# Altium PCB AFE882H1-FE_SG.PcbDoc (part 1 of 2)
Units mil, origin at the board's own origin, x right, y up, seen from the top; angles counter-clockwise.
Board outline 2755.91 x 1181.1 mil, 4 copper layers (Top Layer, Int1 (GND), Int2 (PWR), Bottom Layer), stack 53.912 mil thick; 101 components, 57 nets, 291 pads, 95 vias.
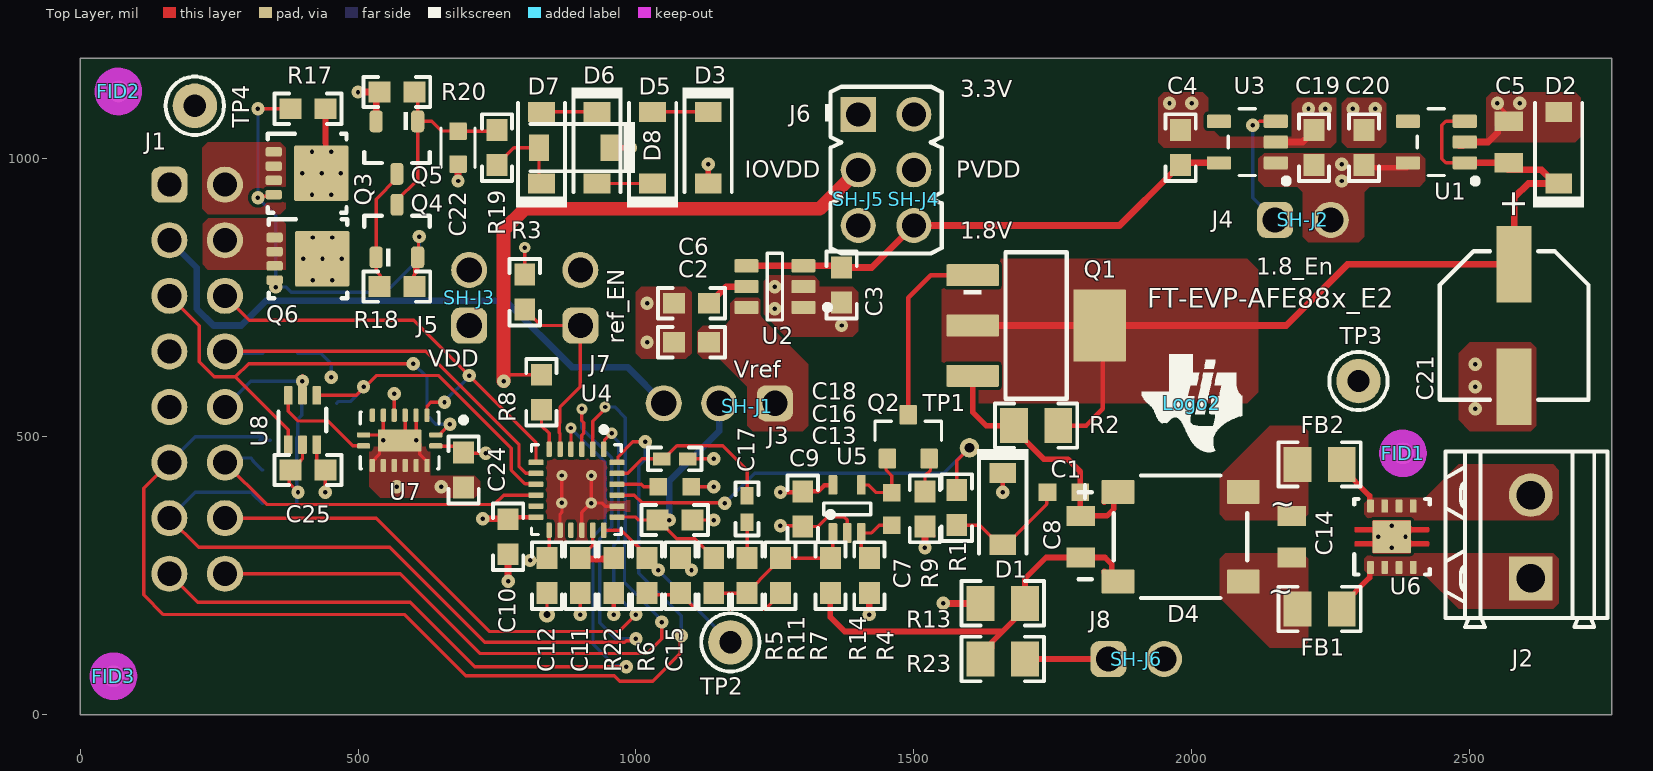
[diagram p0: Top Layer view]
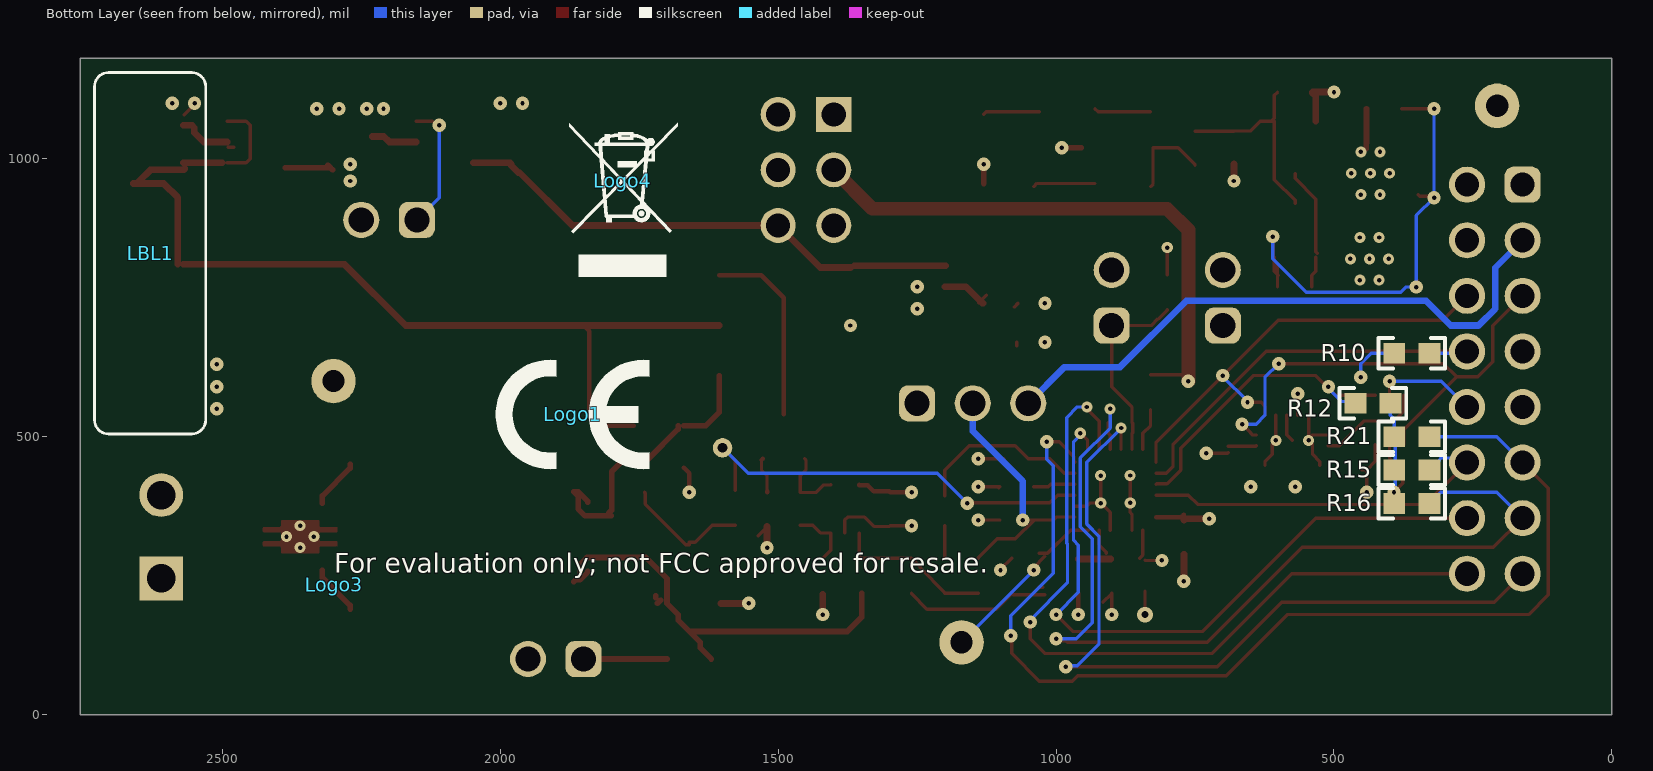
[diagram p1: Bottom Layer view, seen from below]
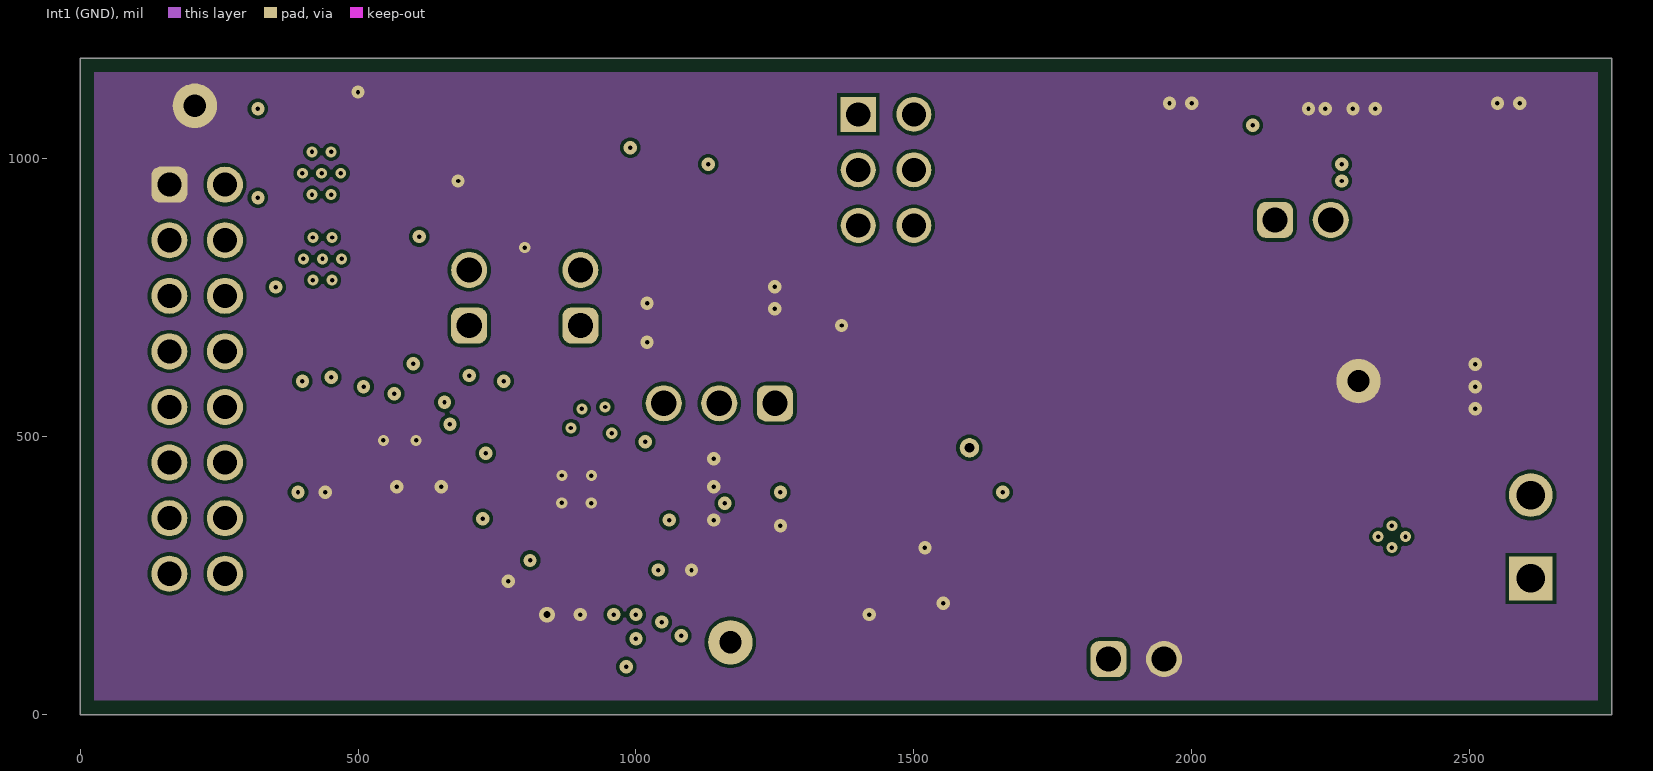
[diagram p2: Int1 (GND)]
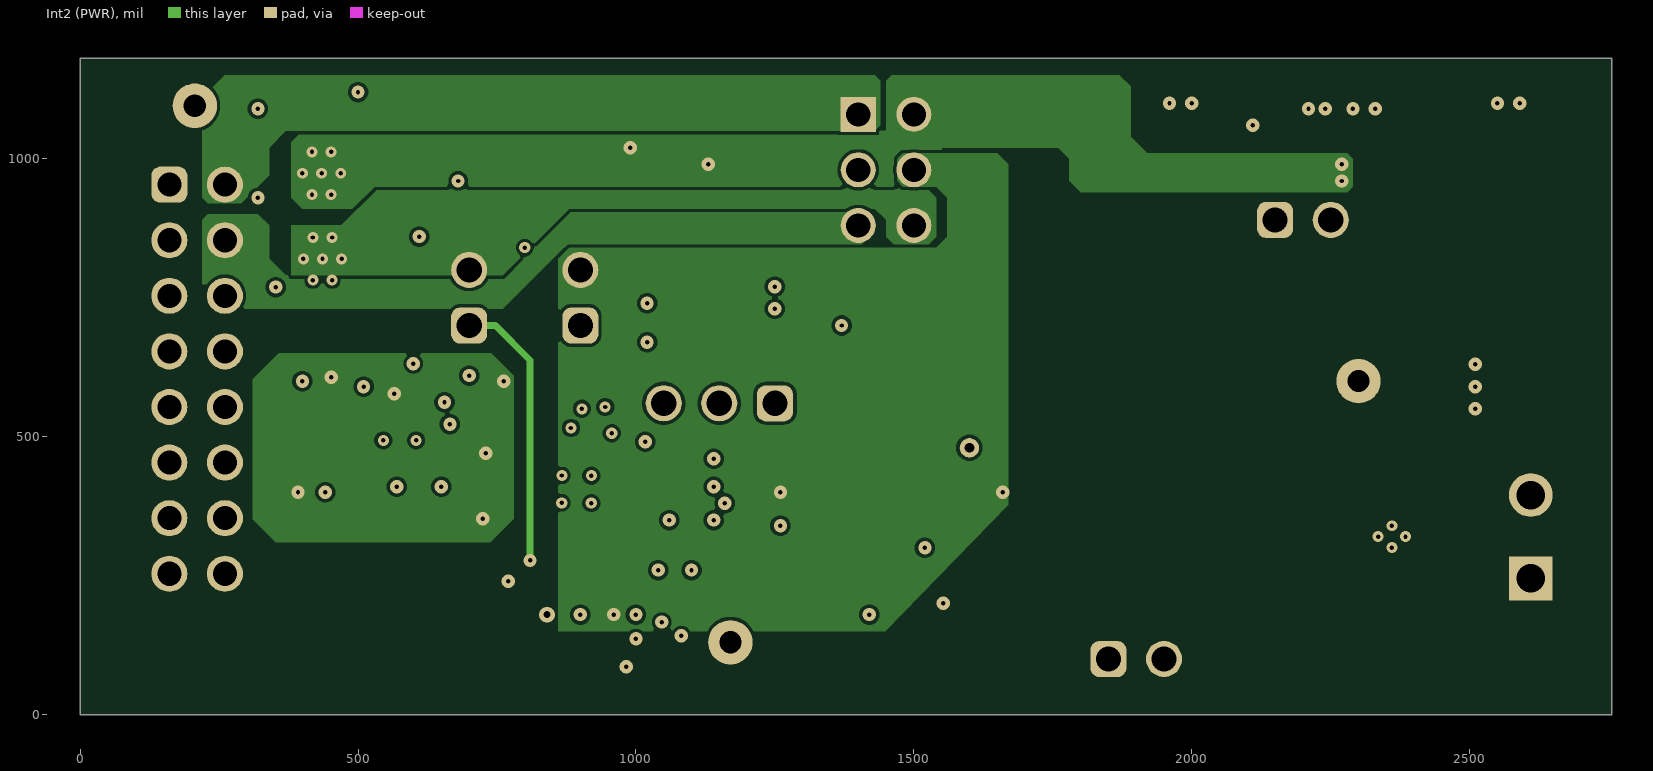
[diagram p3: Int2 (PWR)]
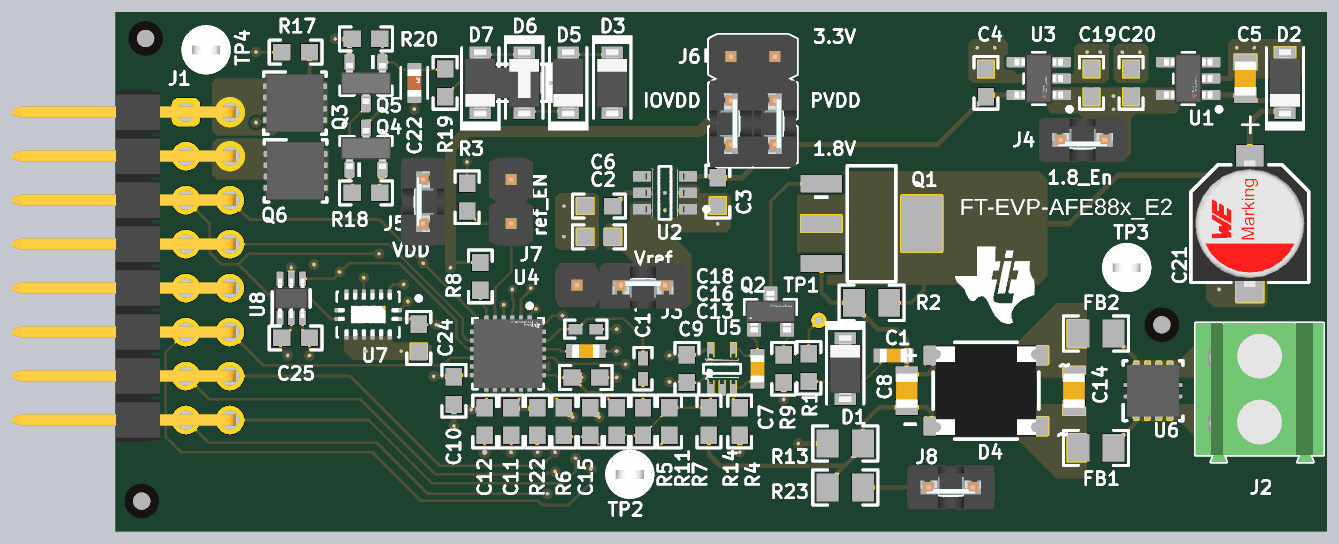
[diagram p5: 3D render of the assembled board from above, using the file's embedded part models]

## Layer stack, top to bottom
Top Solder: solder mask 1, SM-001, Dk 4
Top Layer: signal copper 1.378
Dielectric 1: prepreg 5.1, PP-017, Dk 4.3
Dielectric 2: prepreg 5.1, PP-017, Dk 4.3
Int1 (GND): signal copper 1.378
Dielectric 3: core 28, Core-039, Dk 4.8
Int2 (PWR): signal copper 1.378
Dielectric 4: prepreg 5.1, PP-017, Dk 4.3
Dielectric 5: prepreg 5.1, PP-017, Dk 4.3
Bottom Layer: signal copper 1.378
Bottom Solder: solder mask 1, SM-001, Dk 4

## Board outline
0,0 2755.91,0 2755.91,1181.1 0,1181.1

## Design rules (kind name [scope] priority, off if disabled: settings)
AcuteAngle [All] p1 off: minimum=4.50000000000000E+0001 checktracksonly=FALSE
AssemblyTestPointUsage [All] p1: valid=2
BoardOutlineClearance BoardOutlineClearance_MountingHoles [OnCopper and InComponentClass('Mounting Holes')] p1: gap=39.37 ignorepadtopadclearanceinfootprint=FALSE
BoardOutlineClearance BoardOutlineClearance_Poly [OnCopper and IsPoly] p2: gap=25 ignorepadtopadclearanceinfootprint=FALSE
BoardOutlineClearance [OnCopper and Not InComponentClass('Logo') and not InComponentClass('FiducialMark') and not InRegion(1000,500,4000,800) and not InPoly] p3: gap=40 ignorepadtopadclearanceinfootprint=FALSE
Clearance Clearance_Keepouts [((IsTrack Or IsArc) And Not InPoly) And IsFree and IsKeepOut vs ((IsTrack Or IsArc) And Not InPoly) And IsFree and IsKeepOut] p1: gap=0 ignorepadtopadclearanceinfootprint=FALSE
Clearance Clearance_Poly [InPolygon] p2: gap=6 ignorepadtopadclearanceinfootprint=TRUE
Clearance Clearance_FiducialMark [IsKeepOut and InComponentClass('FiducialMark') vs IsPad and InComponentClass('FiducialMark')] p3: gap=0 ignorepadtopadclearanceinfootprint=FALSE
Clearance [All] p4: gap=6 ignorepadtopadclearanceinfootprint=TRUE
ComponentClearance ComponentClearance_D8_D7_d6 [InComponent('D8') or InComponent('D7') or InComponent('D6')] p1: gap=0 collisioncheckmode=3 verticalgap=0 showdistances=FALSE
ComponentClearance ComponentClearance_J6 [InComponent('J6') or InComponent('SH-J4') or InComponent('SH-J5')] p2: gap=0 collisioncheckmode=3 verticalgap=0 showdistances=FALSE
ComponentClearance ComponentClearance_J5 [InComponent('J5') or InComponent('SH-J3')] p3: gap=0 collisioncheckmode=3 verticalgap=0 showdistances=FALSE
ComponentClearance ComponentClearance_MountingHoles_FiducialMarks [InComponentClass('Mounting Holes') vs InComponentClass('FiducialMark')] p4: gap=50 collisioncheckmode=3 verticalgap=10 showdistances=FALSE
ComponentClearance ComponentClearance_Shunt [InComponentClass('Header') vs InComponentClass('Shunt')] p5: gap=0 collisioncheckmode=3 verticalgap=0 showdistances=FALSE
ComponentClearance ComponentClearance_Logo [InComponentClass('Logo')] p6: gap=30 collisioncheckmode=3 verticalgap=10 showdistances=FALSE
ComponentClearance ComponentClearance_ScrewToNut [(HasFootprint('NY PMS 440 0025 PH')) vs (HasFootprint('Keystone_1902C'))] p7: gap=5 collisioncheckmode=3 verticalgap=10 showdistances=FALSE
ComponentClearance ComponentClearance_MountingHoles [InComponentClass('Mounting Holes')] p8: gap=100 collisioncheckmode=3 verticalgap=100000 showdistances=FALSE
ComponentClearance ComponentClearance_SmallPassives [HasFootprint('0201*') or HasFootprint('0402*') or HasFootprint('0508') or HasFootprint('0603*') or HasFootprint('0612') or HasFootprint('0805*') or HasFootprint('0815*') or HasFootprint('0830*') or HasFootprint('1206*') or HasFootprint('1210*') or HasFootprint('1808*') or HasFootprint('1812*') or HasFootprint('1825*') or HasFootprint('2010*') or HasFootprint('2220*') or HasFootprint('2225*') or HasFootprint('2512*') or HasFootprint('2728*') or HasFootprint('3518*') vs HasFootprint('0201*') or HasFootprint('0402*') or HasFootprint('0508') or HasFootprint('0603*') or HasFootprint('0612') or HasFootprint('0805*') or HasFootprint('0815*') or HasFootprint('0830*') or HasFootprint('1206*') or HasFootprint('1210*') or HasFootprint('1808*') or HasFootprint('1812*') or HasFootprint('1825*') or HasFootprint('2010*') or HasFootprint('2220*') or HasFootprint('2225*') or HasFootprint('2512*') or HasFootprint('2728*') or HasFootprint('3518*')] p9: gap=14.96 collisioncheckmode=3 verticalgap=10 showdistances=FALSE
ComponentClearance ComponentClearance_THtoSMT [IsThruComponent vs IsSMTComponent] p10: gap=20 collisioncheckmode=3 verticalgap=20 showdistances=FALSE
ComponentClearance ComponentClearance_THtoTH [IsThruComponent vs IsThruComponent] p11: gap=20 collisioncheckmode=3 verticalgap=30 showdistances=FALSE
ComponentClearance [All] p12: gap=20 collisioncheckmode=3 verticalgap=10 showdistances=FALSE
DiffPairsRouting [All] p1: maxlimit=100 minlimit=10 mostfreqgap=10 toplayer_minwidth=15 toplayer_maxwidth=15 toplayer_prefwidth=15 midlayer1_minwidth=15 midlayer1_maxwidth=15 midlayer1_prefwidth=15 midlayer2_minwidth=15 midlayer2_maxwidth=15 midlayer2_prefwidth=15 bottomlayer_minwidth=15 bottomlayer_maxwidth=15 bottomlayer_prefwidth=15 maxuncoupledlength=1000
FabricationTestPointUsage TestPointUsage [All] p1: valid=2 allowmultiple=FALSE
FabricationTestpoint Testpoint [All] p1: side=3 testpointundercomponent=TRUE minsize=40 maxsize=100 preferedsize=60 minholesize=0 maxholesize=40 preferedholesize=32 testpointgrid=1 allowsidetop=TRUE allowsidebottom=TRUE usegrid=TRUE gridtolerance=0.01
FanoutControl Fanout_LCC [IsLCC] p1: bgadir=Out bgaviamode=Centered fanoutstyle=Auto fanoutdirection=Alternating viagrid=1 // Fanout_LCC (Default Rule)
FanoutControl Fanout_BGA [IsBGA] p2: bgadir=Out bgaviamode=Centered fanoutstyle=Auto fanoutdirection=Alternating viagrid=1 // Fanout_BGA (Default Rule)
FanoutControl Fanout_Default [All] p4: bgadir=Out bgaviamode=Centered fanoutstyle=Auto fanoutdirection=Alternating viagrid=1 // Fanout_Default (Default Rule)
FanoutControl Fanout_Small [(CompPinCount < 5)] p5: bgadir=Out bgaviamode=Centered fanoutstyle=Auto fanoutdirection=OutThenIn viagrid=1 // Fanout_Small (Default Rule)
HoleSize [All] p1: absolutevalues=TRUE maxlimit=251 minlimit=7.87 maxpercent=80.000 minpercent=20.000
MinimumAnnularRing MinimumAnnularRing_ThermalPadVias [IsVia and InAnyComponent] p1: minimumring=5.91
MinimumAnnularRing [All] p2: minimumring=6
MinimumSolderMaskSliver MinimumSolderMaskSliver_Logo [InComponentClass('Logo') vs InComponentClass('Logo')] p1: minsoldermaskwidth=0.7
MinimumSolderMaskSliver [All] p2: minsoldermaskwidth=3.94
PlaneConnect [All] p1: planeconnectstyle=Relief reliefexpansion=10 reliefentries=4 reliefconductorwidth=10 reliefairgap=10
PolygonConnect PolygonConnect_6 [All vs IsNamedPolygon('TOP_LAYER_GND_P000')] p1: connectstyle=Direct reliefconductorwidth=10 reliefentries=4 polygonreliefangle="90 Angle" airgapwidth=10
PolygonConnect PolygonConnect_5 [All vs IsNamedPolygon('TOP_LAYER_GND_P000')] p2: connectstyle=Direct reliefconductorwidth=10 reliefentries=4 polygonreliefangle="90 Angle" airgapwidth=10
PolygonConnect PolygonConnect_4 [All vs IsNamedPolygon('TOP_LAYER_GND_P001')] p3: connectstyle=Direct reliefconductorwidth=10 reliefentries=4 polygonreliefangle="90 Angle" airgapwidth=10
PolygonConnect PolygonConnect_3 [All vs IsNamedPolygon('TOP_LAYER_GND_P001')] p4: thpad.connectstyle=Direct thpad.reliefconductorwidth=10 thpad.reliefentries=4 thpad.polygonreliefangle="90 Angle" thpad.airgapwidth=10 smdpad.connectstyle=Direct smdpad.reliefconductorwidth=10 smdpad.reliefentries=4 smdpad.polygonreliefangle="90 Angle" smdpad.airgapwidth=10 via.connectstyle=Relief via.reliefconductorwidth=10 via.reliefentries=4 via.polygonreliefangle="90 Angle" via.airgapwidth=10
PolygonConnect PolygonConnect_2 [All vs IsNamedPolygon('TOP_LAYER_NONET_P000')] p5: thpad.connectstyle=Direct thpad.reliefconductorwidth=10 thpad.reliefentries=4 thpad.polygonreliefangle="90 Angle" thpad.airgapwidth=10 smdpad.connectstyle=Direct smdpad.reliefconductorwidth=10 smdpad.reliefentries=4 smdpad.polygonreliefangle="90 Angle" smdpad.airgapwidth=10 via.connectstyle=Relief via.reliefconductorwidth=10 via.reliefentries=4 via.polygonreliefangle="90 Angle" via.airgapwidth=10
PolygonConnect PolygonConnect_1 [All vs IsNamedPolygon('TOP_LAYER_NONET_P000')] p6: thpad.connectstyle=Direct thpad.reliefconductorwidth=10 thpad.reliefentries=4 thpad.polygonreliefangle="90 Angle" thpad.airgapwidth=10 smdpad.connectstyle=Direct smdpad.reliefconductorwidth=10 smdpad.reliefentries=4 smdpad.polygonreliefangle="90 Angle" smdpad.airgapwidth=10 via.connectstyle=Relief via.reliefconductorwidth=10 via.reliefentries=4 via.polygonreliefangle="90 Angle" via.airgapwidth=10
PolygonConnect [All] p7: connectstyle=Direct reliefconductorwidth=10 reliefentries=4 polygonreliefangle="90 Angle" airgapwidth=10
RoutingVias ThermalPadVias [IsVia and InAnyComponent] p1: holewidth=7.87 width=19.68 viastyle="Through Hole" minholewidth=7.87 minwidth=19.68 maxholewidth=12.99 maxwidth=23.62
RoutingVias [All] p2: holewidth=8 width=24 viastyle="Through Hole" minholewidth=8 minwidth=20 maxholewidth=40 maxwidth=65
SilkToBoardRegionClearance [Not ((IsComment or IsDesignator) And (Hide <> 'False')) and not InRegion(1000,500,4000,800)] p1:
SilkToSilkClearance SilkToSilkClearance_Pb-FreeLogo [(HasFootprint('Pb-Free_Overlay_Medium') OR HasFootprint('Pb-Free_Overlay_Small')) vs (HasFootprint('Pb-Free_Overlay_Medium') OR HasFootprint('Pb-Free_Overlay_Small'))] p1 off: silktosilkclearance=0
SilkToSilkClearance [All] p2: silktosilkclearance=3.94
SilkToSolderMaskClearance SilkToComponentPadClearance [(IsPad or IsFill or IsRegion) and InAnycomponent] p1 off: minsilkscreentomaskgap=5 clearancetoexposedcopper=TRUE
SilkToSolderMaskClearance "Silk to Solder Mask Opening" [All] p2 off: minsilkscreentomaskgap=3.94 clearancetoexposedcopper=FALSE
SolderMaskExpansion [All] p1: expansion=1.97 istentingtop=FALSE
SupplyNets "Schematic Supply Nets_8" [InNet('VREF_AFE')] p1: voltage=0.000
SupplyNets "Schematic Supply Nets_7" [InNet('VREF_EXT')] p2: voltage=0.000
SupplyNets "Schematic Supply Nets_5" [InNet('VDD-1V8')] p3: voltage=0.000
SupplyNets "Schematic Supply Nets_4" [InNet('PVDD')] p4: voltage=0.000
SupplyNets "Schematic Supply Nets_3" [InNet('IOVDD')] p5: voltage=0.000
SupplyNets "Schematic Supply Nets_2" [InNet('GND')] p6: voltage=0.000
SupplyNets "Schematic Supply Nets_1" [InNet('VDD_int')] p7: voltage=0.000
SupplyNets "Schematic Supply Nets" [InNet('VDD-3V3')] p8: voltage=0.000
UnRoutedNet [All] p1: checkbadconnections=TRUE
Width [All] p1: maxlimit=100 minlimit=6 preferedwidth=6 minimp=50.000000 maximp=50.000000 favimp=50.000000 checkconnectedcopper=TRUE
14 further rules are at their usual default settings.

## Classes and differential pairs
component class Shunt: SH-J1 SH-J2 SH-J3 SH-J4 SH-J5 SH-J6
component class Logo: Logo2
component class Header: J1 J3 J4 J5 J6 J7 J8
component class AFE882H1-FE_BlankSheet: C1 C2 C3 C4 C5 C6 C7 C8 C9 C10 C11 C12 C13 C14 C15 C16 C17 C18 C19 C20 C21 C22 C24 C25 D1 D2 D3 D4 D5 D6 D7 D8 FB1 FB2 J1 J2 J3 J4 J5 J6 J7 J8 Q1 Q2 Q3 Q4 Q5 Q6 R1 R2 R3 R4 R5 R6 R7 R8 R9 R10 R11 R12 R13 R14 R15 R16 R17 R18 R19 R20 R21 R22 R23 SH-J1 SH-J2 SH-J3 SH-J4 SH-J5 SH-J6 TP1 TP2 TP3 TP4 U1 U2 U3 U4 U5 U6 U7 U8
component class AFE882H1-FE_Hardware: FID1 FID2 FID3 H9 LBL1 Logo1 Logo2 Logo3 Logo4 ZZ1 ZZ2 ZZ3 ZZ4
component class FiducialMark: FID1 FID2 FID3
component class AssemblyNote: ZZ1 ZZ2 ZZ3 ZZ4
component class Label: LBL1

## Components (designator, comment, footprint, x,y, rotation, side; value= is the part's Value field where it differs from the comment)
C1 "885012006015" WCAP-CSGP_0603_L1.6W0.8H0.8_Reflow 1770,400 r0 top value=2.2nF
C2 "885012206052" 0603 1100,670 r180 top value=1uF
C3 "885012206020" 0603 1370,772.83 r270 top value=0.1uF
C4 "885012206052" 0603 1980,1020 r90 top value=1uF
C5 "885012207052" WCAP-CSGP_0805_L2W1.25H1.25 2570,1030 r270 top value=2.2µF
C6 "885012206020" 0603 1100,740 r180 top value=0.1uF
C7 "885012006010" WCAP-CSGP_0603_L1.6W0.8H0.8_Reflow 1460,370 r90 top value=220pF
C8 "885012207086" WCAP-CSGP_0805_L2W1.25H0.8_Reflow 1800,320 r90 top value=1nF
C9 "885012206020" 0603 1300,370 r270 top value=0.1uF
C10 "885012206020" 0603 770,320 r270 top value=0.1uF
C11 "885012206020" 0603 900,250 r270 top value=0.1uF
C12 "885012206052" 0603 840,250 r270 top value=1uF
C13 "885012206020" 0603 1070,350 r0 top value=0.1uF
C14 "885012207086" WCAP-CSGP_0805_L2W1.25H0.8_Reflow 2180,320 r270 top value=1nF
C15 "885012206091" 0603 1080,250 r90 top value=0.022uF
C16 "885012006013" WCAP-CSGP_0603_L1.6W0.8H0.8_Reflow 1070,410 r0 top value=680pF
C17 "885012205061" 0402 1200,370 r90 top value=1000pF
C18 "885012205061" 0402 1070,460 r180 top value=1000pF
C19 "885012206052" 0603 2220,1020 r90 top value=1uF
C20 "885012206052" 0603 2310,1020 r90 top value=1uF
C21 "865230143004" WCAP-AS5H_D6.3H5.5 2580,700 r90 top value=100µF
C22 "885012106005" FP-885012106005_0603-MFG 680,1020 r90 top value=4.7µF
C24 "885012206020" 0603 690,440 r270 top value=0.1uF
C25 "885012206020" 0603 410,440 r0 top value=0.1uF
D1 "1N4148W-TP" SOD-123 1660,370 r270 top value=100V
D2 "MMSZ4688-HE3-08" SOD-123 2660,1020 r90 top value=4.7V
D3 "1N4148W-TP" SOD-123 1130,1020 r270 top value=100V
D4 "CD-MBL206SL" CD-MBL2xxS 1980,320 r0 top value=600V
D5 "1N4148W-TP" SOD-123 1030,1020 r90 top value=100V
D6 "1N4148W-TP" SOD-123 930,1020 r270 top value=100V
D7 "1N4148W-TP" SOD-123 830,1020 r90 top value=100V
D8 "CMHZ4681" SOD-123 890,1020 r180 top value=2.4V
FB1 "742792041" 0805_HV 2230,190 r0 top value="600 ohm"
FB2 "742792041" 0805_HV 2230,450 r0 top value="600 ohm"
FID1 "Fiducial" Fiducial10-20 2380,470 r0 top
FID2 "Fiducial" Fiducial10-20 68.9,1121.1 r0 top
FID3 "Fiducial" Fiducial10-20 60,68.9 r0 top
J1 "61301621021" Wurth_61301621021 210.52,603.39 r0 top
J2 "691214310002" Wurth_691214310002 2610,320 r90 top
J3 "61300311121" WURTH_61300311121 1150,560 r180 top
J4 "61300211121" WURTH_61300211121 2200,890 r0 top
J5 "61300211121" WURTH_61300211121 700,750 r90 top
J6 "61300621121" Wurth_61300621121 1450,980 r0 top
J7 "61300211121" WURTH_61300211121 900,750 r90 top
J8 "61300211121" WURTH_61300211121 1900,100 r0 top
LBL1 "THT-14-423-10" Label_650x200 2630,830 r90 bottom
Logo1 "CE Mark" CE_Mark_5mm 1870,540 r180 bottom
Logo2 "Texas Instruments" TI_Symbol_Overlay_Small 2000,560 r0 top
Logo3 "FCC disclaimer" FCC_disclaimer 2298.43,233.22 r180 bottom
Logo4 "WEEE logo" WEEE_Minimum 1780,960 r180 bottom
Q1 "PZT2907A" SOT-223 1720,700 r0 top value="60 V"
Q2 "SMMBT3904LT3G" FP-SMMBT3904LT3G_SOT23-MFG 1490,500 r90 top value=40V
Q3 "CSD25404Q3" DQG0008A 408.35,973.92 r0 top value=-20V
Q4 "BC858CLT1G" SOT-23 570,870 r90 top value="30 V"
Q5 "BC847CLT1G" SOT-23 570,1020 r270 top value="45 V"
Q6 "CSD25404Q3" DQG0008A 410,820 r0 top value=-20V
R1 "RC0603JR-071KL" 0603 1577.06,372.39 r270 top value=1.0k
R2 "RG2012P-123-B-T5" 0805_HV 1720,520 r180 top value=12.0k
R3 "RC0603FR-072M21L" 0603 800,760 r90 top value=2.21Meg
R4 "RG1608P-203-B-T5" 0603 1420,250 r90 top value=20.0k
R5 "RT0603BRD07412KL" 0603 1140,250 r270 top value=412k
R6 "RG1608P-203-B-T5" 0603 1020,250 r90 top value=20.0k
R7 "RG1608P-104-B-T5" 0603 1260,250 r90 top value=100k
R8 "CRCW06031M00JNEA" 0603 830,580 r90 top value=1.0Meg
R9 "RT0603BRD074K99L" 0603 1520,370 r90 top value=4.99k
R10 "CRCW06031M00JNEA" 0603 360,650 r0 bottom value=1.0Meg
R11 "RT0603DRE07499KL" 0603 1200,250 r270 top value=499k
R12 "CRCW06031M00JNEA" 0603 430,560 r180 bottom value=1.0Meg
R13 "RT0805BRD0720RL" 0805_HV 1660,200 r180 top value=20.0
R14 "RG1608P-203-B-T5" 0603 1350,250 r90 top value=20.0k
R15 "CRCW06031M00JNEA" 0603 360,440 r0 bottom value=1.0Meg
R16 "CRCW06031M00JNEA" 0603 360,380 r0 bottom value=1.0Meg
R17 "CRCW06031M00JNEA" 0603 410,1090 r0 top value=1.0Meg
R18 "M55342K12B10E0T" 0603 570,770 r0 top value=10.0k
R19 "M55342K12B10E0T" 0603 750,1020 r270 top value=10.0k
R20 "M55342K12B10E0T" 0603 570,1120 r0 top value=10.0k
R21 "M55342K12B10E0T" 0603 360,500 r0 bottom value=10.0k
R22 "RCS06030000Z0EA" 0603 960,250 r90 top value=0
R23 "RT0805BRD0720RL" 0805_HV 1660,100 r0 top value=20.0
SH-J1 "60900213421" Wurth_60900213421 1200,555 r0 top
SH-J2 "60900213421" Wurth_60900213421 2200,890 r180 top
SH-J3 "60900213421" Wurth_60900213421 700,750 r90 top
SH-J4 "60900213421" Wurth_60900213421 1500,927.48 r270 top
SH-J5 "60900213421" Wurth_60900213421 1400,927.48 r270 top
SH-J6 "60900213421" Wurth_60900213421 1900,100 r180 top
TP1 "TP_H0.45P0.75" TP_H045P075 1600,480 r0 top
TP2 "VOUT" Keystone5002 1170,130 r90 top
TP3 "GND" Keystone5002 2300,600 r90 top
TP4 "GND" Keystone5002 206.4,1095.28 r90 top
U1 "TPS7A0333DBVR" DBV0005A-MFG 2440,1030 r180 top
U2 "REF35125QDBVR" DBV0006A-MFG 1250,770 r180 top
U3 "TPS7A0318DBVR" DBV0005A-MFG 2100,1030 r180 top
U4 "AFE882H1RRUT" RRU0024A-MFG 892.98,404.55 r270 top
U5 "OPA391DCKT" DCK0005A-MFG 1380,370 r90 top
U6 "TVS3301DRBR" DRB0008A 2360,320 r90 top
U7 "SN74LV8T165BQBR" BQB0016A-MFG 575,493.29 r270 top
U8 "TMUX1219DCKR" DCK0006A_N 400,530 r90 top
ZZ1 "This Assembly Note is for PCB labels only" AssemblyNoteLabel 185,3938 r0 top
ZZ2 "These assemblies are ESD sensitive, ESD precautions shall be observed." AssemblyNote 185,3829.11 r0 top
ZZ3 "These assemblies must be clean and free from flux and all contaminants. Use of no clean flux is not acceptable." AssemblyNote 185,3740.56 r0 top
ZZ4 "These assemblies must comply with workmanship standards IPC-A-610 Class 2, unless otherwise specified." AssemblyNote 185,3652 r0 top

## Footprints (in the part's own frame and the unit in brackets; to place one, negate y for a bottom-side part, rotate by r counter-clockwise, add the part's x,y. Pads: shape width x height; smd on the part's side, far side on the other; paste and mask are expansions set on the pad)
0402 [mm] "0402 from SM-752 data"
  rect 0.8x0.6 smd: 1(-0.6,0) 2(0.6,0)
  silkscreen extent -1.22,-0.52 1.22,0.52, body extent -0.55,-0.3 0.55,0.3, height 0.6
0603 [mm] "0603 from SM-752 data"
  rect 1x0.95 smd: 1(-0.8,0) 2(0.8,0)
  silkscreen extent -1.52,-0.69 1.52,0.69, body extent -0.87,-0.47 0.87,0.47, height 1
0805_HV [mil] "0805 with 30mil clearance between pads"
  rect 50x63 smd: 1(-40,0) 2(40,0)
  silkscreen extent -74,-40 74,40, body extent -43,-29 43,29, height 57
AssemblyNote [mil] "Assembly Note"
AssemblyNoteLabel [mil] "Assembly Note for PCB Labels"
BQB0016A-MFG [mm]
  rrect42% 0.24x0.6 smd paste+0 mask+0: 1(-0.25,1.65) 8(-0.25,-1.65) 9(0.25,-1.65) 16(0.25,1.65)
  rrect42% 0.6x0.24 smd paste+0 mask+0: 2(-1.15,1.25) 3(-1.15,0.75) 4(-1.15,0.25) 5(-1.15,-0.25) 6(-1.15,-0.75) 7(-1.15,-1.25) 10(1.15,-1.25) 11(1.15,-0.75) 12(1.15,-0.25) 13(1.15,0.25) 14(1.15,0.75) 15(1.15,1.25)
  rrect10% 1x2 smd paste-1000 mask+0: 17(0,0)
  silkscreen extent -1.3,-1.8 1.3,3.05, body extent -1.55,-2.05 1.55,2.05, height 0.25
CD-MBL2xxS [mm] "SMD, 4-Leads, Body 5.72x4.1mm"
  rrect9% 1.5x1.1 smd: 1(-2.86,2.05) 2(2.86,2.05) 3(2.86,-2.05) 4(-2.86,-2.05)
  silkscreen extent -4.67,-2.8 3.05,2.8, body extent -2.9,-2.65 2.9,2.65, height 1.02
CE_Mark_5mm [mil] "Minimum text height for CE Mark"
  silkscreen extent -138,-98 138,98
DBV0005A-MFG [mm]
  rrect17% 1.1x0.6 smd paste+0 mask+0: 1(-1.3,0.95) 2(-1.3,0) 3(-1.3,-0.95) 4(1.3,-0.95) 5(1.3,0.95)
  silkscreen extent -1.9,-1.52 0.87,1.9, body extent -1.95,-1.78 1.95,1.78, height 0.25
DBV0006A-MFG [mm]
  rrect17% 1.1x0.6 smd paste+0 mask+0: 1(-1.3,0.95) 2(-1.3,0) 3(-1.3,-0.95) 4(1.3,-0.95) 5(1.3,0) 6(1.3,0.95)
  silkscreen extent -2.53,-1.53 0.35,1.52, body extent -1.95,-1.78 1.95,1.78, height 0.25
DCK0005A-MFG [mm]
  rrect25% 0.9x0.4 smd paste-1000 mask+0: 1(-1.1,0.65) 2(-1.1,0) 3(-1.1,-0.65) 4(1.1,-0.65) 5(1.1,0.65)
  silkscreen extent -0.38,-1.07 0.27,1.08, body extent -1.65,-1.33 1.65,1.33, height 0.25
DCK0006A_N [mm] "SOT23, 6-Leads, Body 2x1.3mm, Pitch 0.65mm, Lead Span 2.1mm, IPC Medium Density"
  rrect25% 0.85x0.4 smd: 1(-1.125,0.65) 2(-1.125,0) 3(-1.125,-0.65) 4(1.125,-0.65) 5(1.125,0) 6(1.125,0.65)
  silkscreen extent -1.5,-1.09 0.51,1.09, body extent -1.14,-1 1.14,1, height 0.95
DQG0008A [mm] "SMD, 8-Leads, Body 3.3x3.3mm, Pitch 0.65mm"
  rrect45% 0.75x0.44 smd paste-0.05 mask-0.05: 1(-1.525,0.975) 2(-1.525,0.325) 3(-1.525,-0.325) 4(-1.525,-0.975) 5(1.525,-0.975) 6(1.525,-0.325) 7(1.525,0.325) 8(1.525,0.975)
  rrect15% 0.676x1.125 on Top Paste: 9(-0.212,-0.663) 9(-0.212,0.662) 9(0.664,-0.663) 9(0.664,0.662)
  rrect6% 1.775x2.45 on Top Solder: 9(0.327,0)
  rrect8% 2.5x2.55 smd paste-1.5 mask-1.5: 9(0.65,0)
  rrect29% 0.5x0.34 on Top Solder: 9(1.175,-0.975) 9(1.175,-0.325) 9(1.175,0.325) 9(1.175,0.975)
  silkscreen extent -1.8,-1.8 1.8,1.8, body extent -1.65,-1.65 1.65,1.65, height 1.1
DRB0008A [mm] "VSON-8"
  rrect32% 0.6x0.31 smd: 1(-1.4,0.975) 2(-1.4,0.325) 3(-1.4,-0.325) 4(-1.4,-0.975) 5(1.4,-0.975) 6(1.4,-0.325) 7(1.4,0.325) 8(1.4,0.975)
  rrect7% 1.5x1.75 smd paste-0.75: 9(0,0)
  Top Layer region: -0.7,-0.875 -0.49,-0.875 -0.471,-0.879 -0.455,-0.89 -0.444,-0.906 -0.44,-0.925 -0.44,-0.925 -0.44,-1.65 -0.436,-1.669 -0.425,-1.685 -0.409,-1.696 -0.39,-1.7 -0.39,-1.7 -0.26,-1.7 -0.241,-1.696 -0.225,-1.685 -0.214,-1.669 -0.21,-1.65 -0.21,-1.65 -0.21,-0.925 -0.206,-0.906 -0.195,-0.89 -0.179,-0.879 -0.16,-0.875 -0.16,-0.875 0.16,-0.875 0.179,-0.879 0.195,-0.89 0.206,-0.906 0.21,-0.925 0.21,-0.925 0.21,-1.65 0.21,-1.65 0.214,-1.669 0.225,-1.685 0.241,-1.696 0.26,-1.7 0.26,-1.7 0.39,-1.7 0.409,-1.696 0.425,-1.685 0.436,-1.669 0.44,-1.65 0.44,-1.65 0.44,-0.925 0.444,-0.906 0.455,-0.89 0.471,-0.879 0.49,-0.875 0.49,-0.875 0.7,-0.875 0.719,-0.871 0.735,-0.86 0.746,-0.844 0.75,-0.825 0.75,-0.825 0.75,0.825 0.746,0.844 0.735,0.86 0.719,0.871 0.7,0.875 0.7,0.875 0.49,0.875 0.471,0.879 0.455,0.89 0.444,0.906 0.44,0.925 0.44,0.925 0.44,1.65 0.436,1.669 0.425,1.685 0.409,1.696 0.39,1.7 0.39,1.7 0.26,1.7 0.241,1.696 0.225,1.685 0.214,1.669 0.21,1.65 0.21,1.65 0.21,1.65 0.21,0.925 0.206,0.906 0.195,0.89 0.179,0.879 0.16,0.875 0.16,0.875 -0.16,0.875 -0.179,0.879 -0.195,0.89 -0.206,0.906 -0.21,0.925 -0.21,0.925 -0.21,1.65 -0.214,1.669 -0.225,1.685 -0.241,1.696 -0.26,1.7 -0.26,1.7 -0.39,1.7 -0.409,1.696 -0.425,1.685 -0.436,1.669 -0.44,1.65 -0.44,1.65 -0.44,0.925 -0.444,0.906 -0.455,0.89 -0.471,0.879 -0.49,0.875 -0.49,0.875 -0.7,0.875 -0.719,0.871 -0.735,0.86 -0.746,0.844 -0.75,0.825 -0.75,0.825 -0.75,-0.825 -0.746,-0.844 -0.735,-0.86 -0.719,-0.871 -0.7,-0.875
  silkscreen extent -1.73,-1.73 1.73,1.73, body extent -1.5,-1.5 1.5,1.5, height 0.77
FCC_disclaimer [mil]
Fiducial10-20 [mm]
  round 1 smd mask+0.5: 1(0,0)
  Top Layer keep-out circle w1.178: c0,0 r0.5
FP-885012106005_0603-MFG [mm]
  rrect13% 0.8x0.8 smd paste+0 mask+0: 1(-0.75,0) 2(0.75,0)
  silkscreen extent -0.9,-0.77 0.9,0.77, body extent -1.25,-0.6 1.25,0.6, height 0.25
FP-SMMBT3904LT3G_SOT23-MFG [mm]
  rrect13% 0.9x0.8 smd paste+0 mask+0: 1(-1,0.95) 2(-1,-0.95) 3(1,0)
  silkscreen extent -0.18,-1.52 0.7,1.52, body extent -1.55,-1.62 1.55,1.62, height 0.25
Keystone5002 [mil] "For Keystone 500x miniature loop terminals"
  round 80 hole 40: 1(0,0)
  silkscreen extent -52,-52 52,52, body extent -49,-49 49,49, height 182
Label_650x200 [mil] "Thermal Transfer Label"
  round 1 on Mech14: 0(0,0)
  silkscreen extent -325,-100 325,100, body extent -325,-100 325,100, height 1
RRU0024A-MFG [mm]
  rrect40% 0.7x0.25 smd paste+0 mask+0: 1(-1.85,1.25) 2(-1.85,0.75) 3(-1.85,0.25) 4(-1.85,-0.25) 5(-1.85,-0.75) 6(-1.85,-1.25) 13(1.85,-1.25) 14(1.85,-0.75) 15(1.85,-0.25) 16(1.85,0.25) 17(1.85,0.75) 18(1.85,1.25)
  rrect40% 0.25x0.7 smd paste+0 mask+0: 7(-1.25,-1.85) 8(-0.75,-1.85) 9(-0.25,-1.85) 10(0.25,-1.85) 11(0.75,-1.85) 12(1.25,-1.85) 19(1.25,1.85) 20(0.75,1.85) 21(0.25,1.85) 22(-0.25,1.85) 23(-0.75,1.85) 24(-1.25,1.85)
  silkscreen extent -2.87,-2.05 2.05,2.05, body extent -2.3,-2.3 2.3,2.3, height 0.25
SOD-123 [mm] "On Semi recommended land pattern"
  rect 0.915x1.22 smd: 1(-1.638,0) 2(1.637,0)
  silkscreen extent -2.74,-1.17 2.03,1.17, body extent -1.93,-0.9 1.93,0.9, height 1.35
SOT-23 [mm] "SOT23, 3-Leads, Body 2.9x1.3mm, Pitch 0.95mm, Lead Span 2.5mm, IPC Medium Density"
  rrect50% 1x0.6 smd: 1(-1.2,0.95) 2(-1.2,-0.95) 3(1.2,0)
  silkscreen extent -1.63,-1.5 0.7,1.5, body extent -1.16,-1.45 1.21,1.45, height 1
SOT-223 [mm] "SOT223/SC73, 4-Leads, Body 6.5x3.5mm, Pitch 2.3mm, Lead Span 7mm, IPC Medium Density"
  rrect10% 2.4x1 smd: 1(-2.9,2.3) 2(-2.9,0) 3(-2.9,-2.3)
  rrect4% 2.4x3.3 smd: 4(2.9,0)
  silkscreen extent -3.32,-3.35 1.4,3.35, body extent -3.5,-3.25 3.5,3.25, height 1.62
TI_Symbol_Overlay_Small [mil]
  silkscreen extent -90,-88 91,88
TP_H045P075 [mil] "TP_H0.45P0.75"
  round 35 hole 17.72: 1(0,0)
WCAP-AS5H_D6.3H5.5 [mm] "Aluminum Electrolytic Capacitors, 6.3x5.5mm"
  rect 3.5x1.6 smd: 1(2.8,0) 2(-2.8,0)
  silkscreen extent -3.4,-3.4 3.4,3.4, body extent -3.65,-3.3 3.65,3.3, height 5.5
WCAP-CSGP_0603_L1.6W0.8H0.8_Reflow [mm] "Ceramic Capacitors, body 1.6x0.8mm"
  rect 0.8x0.8 smd: 1(-0.75,0) 2(0.75,0)
  body extent -0.8,-0.4 0.8,0.4, height 0.8
WCAP-CSGP_0805_L2W1.25H0.8_Reflow [mm] "Ceramic Capacitors, body 2x1.25mm"
  rect 0.9x1.3 smd: 1(-0.95,0) 2(0.95,0)
  body extent -1,-0.62 1,0.63, height 0.8
WCAP-CSGP_0805_L2W1.25H1.25 [mm] "Ceramic Capacitors, body 2x1.25mm"
  rect 0.9x1.3 smd: 1(-0.95,0) 2(0.95,0)
  body extent -1,-0.63 1,0.63, height 1.25
WEEE_Minimum [mil] "WEEElie bin"
  silkscreen extent -95,-172 99,104
Wurth_60900213421 [mil] "Shunt, 2.54mm, Black"
  round 1 on Mech3: 0(0,0)
  body extent -98,-48 98,48, height 338
WURTH_61300211121 [mm] "Header, 2.54mm, 2x1, TH"
  rrect50% 1.65x1.65 hole 1.15: 1(-1.27,0)
  round 1.65 hole 1.15: 2(1.27,0)
  body extent -2.54,-1.27 2.54,1.27, height 8.54
WURTH_61300311121 [mm] "Header, 2.54mm, 3x1, TH"
  rrect50% 1.65x1.65 hole 1.15: 1(-2.54,0)
  round 1.65 hole 1.15: 2(0,0) 3(2.54,0)
  body extent -3.81,-1.27 3.81,1.27, height 8.54
Wurth_61300621121 [mm] "Header, 2.54mm, 3x2, TH"
  rect 1.6x1.6 hole 1.1: 1(-1.27,2.54)
  round 1.6 hole 1.1: 2(1.27,2.54) 3(-1.27,0) 4(1.27,0) 5(-1.27,-2.54) 6(1.27,-2.54)
  silkscreen extent -2.8,-3.82 2.54,3.8, body extent -2.54,-3.82 2.54,3.8, height 7.27
Wurth_61301621021 [mm] "Header, 2.54mm, 8x2, R/A, TH"
  rrect50% 1.65x1.65 hole 1.1: 1(-1.27,8.89)
  round 1.65 hole 1.1: 2(1.27,8.89) 3(-1.27,6.35) 4(1.27,6.35) 5(-1.27,3.81) 6(1.27,3.81) 7(-1.27,1.27) 8(1.27,1.27) 9(-1.27,-1.27) 10(1.27,-1.27) 11(-1.27,-3.81) 12(1.27,-3.81) 13(-1.27,-6.35) 14(1.27,-6.35) 15(-1.27,-8.89) 16(1.27,-8.89)
  body extent -11.31,-10.16 1.59,10.16, height 5.08
Wurth_691214310002 [mm] "WE"
  rect 2x2 hole 1.3: 1(-1.905,0)
  round 2 hole 1.3: 2(1.905,0)
  silkscreen extent -4.12,-3.5 3.9,3.9, body extent -4.12,-3.5 3.9,3.9, height 8.52

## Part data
C1: library part CMP-0107759-1, "WCAP-CSGP Multilayer Ceramic Chip Capacitor, General Purpose, size 0603, NP0, 2.2nF, 10VDC", Capacitance Tolerance=+/-5%, Case/Size Code=0603, Insulation Resistance=10GOhm, Manufacturer="Wurth Elektronik", Operating Temperature Max=125°C, Operating Temperature Min=-55°C, Rated Voltage (DC)=10V
C2 C4 C12 C19 C20: library part CMP-0006831-4, "CAP, CERM, 1 uF, 16 V, +/- 10%, X7R, 0603", Cap_Case=0603, Manufacturer="Wurth Elektronik", Supplier Part Number 1=710-885012206052, TempCo=X7R, Tolerance_%=10%, Value1=Unknown, Value2=16V, ValueDisplayed=1uF
C3 C6 C9 C10 C11 C13 C24 C25: library part CMP-0064931-4, "CAP, CERM, 0.1 uF, 10 V,+/- 10%, X7R, 0603", Cap_Case=0603, Manufacturer="Wurth Elektronik", Supplier Part Number 1=732-7939-1-ND, TempCo=X7R, Tolerance_%=10%, Value1=Unknown, Value2=10V, ValueDisplayed=0.1uF
C5: library part CMP-0115546-1, "WCAP-CSGP Multilayer Ceramic Chip Capacitor, General Purpose, size 0805, X7R, 2.2µF, 16VDC", Capacitance Tolerance=+/-10%, Case/Size Code=0805, Insulation Resistance=0.05GOhm, Manufacturer="Wurth Elektronik", Operating Temperature Max=125°C, Operating Temperature Min=-55°C, Rated Voltage (DC)=16V
C7: library part CMP-0114923-1, "WCAP-CSGP Multilayer Ceramic Chip Capacitor, General Purpose, size 0603, NP0, 220pF, 10VDC", Capacitance Tolerance=+/-5%, Case/Size Code=0603, Insulation Resistance=10GOhm, Manufacturer="Wurth Elektronik", Operating Temperature Max=125°C, Operating Temperature Min=-55°C, Rated Voltage (DC)=10V
C8 C14: library part CMP-0104837-1, "WCAP-CSGP Multilayer Ceramic Chip Capacitor, General Purpose, size 0805, X7R, 1nF, 50VDC", Capacitance Tolerance=+/-10%, Case/Size Code=0805, Insulation Resistance=10GOhm, Manufacturer="Wurth Elektronik", Operating Temperature Max=125°C, Operating Temperature Min=-55°C, Rated Voltage (DC)=50V
C15: library part CMP-0006836-4, "CAP, CERM, 0.022 uF, 50 V, +/- 10%, X7R, 0603", Cap_Case=0603, Manufacturer="Wurth Elektronik", TempCo=X7R, Tolerance_%=10%, Value1=Unknown, Value2=50V, ValueDisplayed=0.022uF
C16: library part CMP-0104183-1, "WCAP-CSGP Multilayer Ceramic Chip Capacitor, General Purpose, size 0603, NP0, 680pF, 10VDC", Capacitance Tolerance=+/-5%, Case/Size Code=0603, Insulation Resistance=10GOhm, Manufacturer="Wurth Elektronik", Operating Temperature Max=125°C, Operating Temperature Min=-55°C, Rated Voltage (DC)=10V
C17 C18: library part CMP-0006231-2, "CAP, CERM, 1000 pF, 50 V, +/- 10%, X7R, 0402", Cap_Case=0402, Manufacturer="Wurth Elektronik", Supplier Part Number 1=732-7556-1-ND, TempCo=X7R, Tolerance_%=10%, Value1=Unknown, Value2=50V, ValueDisplayed=1000pF
C21: library part CMP-0107158-1, "WCAP-AS5H Aluminum Electrolytic Capacitor, V-Chip, D6.3 x H5.5mm, 100µF, 6.3V", Capacitance Tolerance=+/-20%, Leakage Current=6.3uA, Manufacturer="Wurth Elektronik", Operating Temperature Max=105°C, Operating Temperature Min=-40°C, Rated Voltage (DC)=6.3V, Ripple Current=60mA
C22: library part CMP-0049191-1, "4.7 µF ±20% 6.3V Ceramic Capacitor X5R 0603 (1608 Metric)", Digikey Part Number=732-7902-1-ND, Manufacturer="Wurth Electronics", Mouser Part Number=710-885012106005, Operating Temperature Range="-55°C to +85°C", TempCo=15%, Temperature Characteristic=X5R, Tolerance_%=20%, ValueDisplayed=4.7uF
D1 D3 D5 D6 D7: library part CMP-0076974-2, "Diode, Switching, 100 V, 0.15 A, SOD-123", Manufacturer="Micro Commercial Components", Value1=0.15A, Value2=1.25V
D2: library part CMP-0077561-3, "Diode, Zener, 4.7 V, 500 mW, AEC-Q101, SOD-123", Manufacturer=Vishay-Semiconductor, Power_W=500mW, Value1=0.5W
D4: library part CMP-0067544-2, "Diode, P-N-Bridge, 600 V, 2 A, 5.8x5.3mm", Manufacturer=Bourns, Value1=2A, Value2=0.96V
D8: library part CMP-0085120-1, "Diode, Zener, 3 V, 500 mW, AEC-Q101, SOD-123", Power_W=500mW, Value1=0.5W
FB1 FB2: library part CMP-0003085-1, "Ferrite Bead, 600 ohm @ 100 MHz, 0.2 A, 0805", Manufacturer="Wurth Elektronik", Supplier Part Number 1=732-1604-1-ND, Value1="0.4 ohm", Value2=0.2A, ValueDisplayed="600 ohm"
FID1 FID2 FID3: library part CMP-0077181-1, "Fiducial mark.  There is nothing to buy or mount.", Manufacturer=N/A
J1: library part CMP-0081505-1, "Header, 2.54mm, 8x2, Gold, R/A, TH", Color=Black, Current_A=3A, Manufacturer="Wurth Elektronik", Supplier Part Number 1=732-5356-ND, Voltage_V=250V
J2: library part CMP-0054822-2, "Terminal Block, 2x1, 3.81mm, 24-16 AWG, 10A, 300VAC, TH", Manufacturer="Wurth Elektronik"
J3: library part CMP-0054796-4, "Header, 2.54 mm, 3x1, Gold, TH", Manufacturer="Wurth Elektronik", Supplier Part Number 1=732-5316-ND
J4 J5 J7 J8: library part CMP-0054794-2, "Header, 2.54 mm, 2x1, Gold, TH", Color=Black, Manufacturer="Wurth Elektronik", Supplier Part Number 1=732-5315-ND
J6: library part CMP-0054802-2, "Header, 2.54mm, 3x2, Gold, TH", Color=Black, Manufacturer="Wurth Elektronik", Supplier Part Number 1=732-5295-ND
LBL1: library part CMP-0003625-1, "Thermal Transfer Printable Labels, 0.650\" W x 0.200\" H - 10,000 per roll", Manufacturer=Brady, Supplier Part Number 1=97C5133
Logo1: library part CMP-0074844-1
Logo2: library part CMP-0074838-1, "Texas Instrument Corporate Signature"
Logo3: library part CMP-0074847-1, "FCC_disclaimer"
Logo4: library part CMP-0074769-1
Q1: library part CMP-0000355-2, "Transistor, PNP, 60 V, 0.8 A, SOT-223", Manufacturer="Fairchild Semiconductor", Supplier Part Number 1=PZT2907ACT-ND, Value1="0.8 A", Value2=300
Q2: library part CMP-0097440-1, "Bipolar (BJT) Transistor NPN 40 V 200 mA 300MHz 300 mW Surface Mount SOT-23-3 (TO-236)", Collector Base Voltage=60V, Digikey Part Number=SMMBT3904LT3GOSCT-ND, Emitter Base Voltage=6V, Manufacturer="On Semiconductor", Mouser Part Number=863-SMMBT3904LT3G, Operating Temperature Range="-55°C to +150°C", Power_W=225mW, Unity Gain Freq=300MHz
Q3 Q6: library part CMP-0000026-3, "MOSFET, P-CH, -20 V, -60 A, DQG0008A (VSON-CLIP-8)", Alternate Manufacturer=None, Manufacturer="Texas Instruments", Value1=0.006, Value2="10.8 nC"
Q4: library part CMP-0000342-2, "Transistor, PNP, 30 V, 0.1 A, SOT-23", Manufacturer="ON Semiconductor", Supplier Part Number 1=BC858CLT1GOSCT-ND, Value1="0.1 A", Value2=800
Q5: library part CMP-0000376-2, "Transistor, NPN, 45 V, 0.1 A, SOT-23", Manufacturer="ON Semiconductor", Supplier Part Number 1=BC847CLT1GOSCT-ND, Value1="0.1 A", Value2=800
R1: library part CMP-0025899-5, "RES, 1.0 k, 5%, 0.1 W, 0603", Manufacturer=Yageo, Power_W=100mW, Supplier Part Number 1=311-1.0KGRCT-ND, TempCo="100 ppm/C", Tolerance_%=5%, Value2=0.1W, Value_Code=1k00, ValueDisplayed=1.0k
R2: library part CMP-0018871-2, "RES, 12.0 k, 0.1%, 0.125 W, 0805", Manufacturer="Susumu Co Ltd", Power_W=125mW, Supplier Part Number 1=RG20P12.0KBCT-ND, TempCo="25 ppm/C", Tolerance_%=0.1%, Value2=0.125W, Value_Code=12k0, ValueDisplayed=12.0k
R3: library part CMP-0023001-4, "RES, 2.21 M, 1%, 0.1 W, 0603", Manufacturer=Yageo, Power_W=100mW, Supplier Part Number 1=311-2.21MHRCT-ND, TempCo="100 ppm/C", Tolerance_%=1%, Value2=0.1W, Value_Code=2M21, ValueDisplayed=2.21M
R4 R6 R14: library part CMP-0023464-3, "RES, 20.0 k, 0.1%, 0.1 W, 0603", Manufacturer="Susumu Co Ltd", Power_W=100mW, Supplier Part Number 1=RG16P20.0KBCT-ND, TempCo="25 ppm/C", Tolerance_%=0.1%, Value2=0.1W, Value_Code=20k0, ValueDisplayed=20.0k
R5: library part CMP-0024218-3, "RES, 412 k, 0.1%, 0.1 W, 0603", Manufacturer="Yageo America", Power_W=100mW, TempCo="25 ppm/C", Tolerance_%=0.1%, Value2=0.1W, Value_Code=412k
R7: library part CMP-0023405-3, "RES, 100 k, 0.1%, 0.1 W, 0603", Manufacturer="Susumu Co Ltd", Power_W=100mW, Supplier Part Number 1=RG16P100KBCT-ND, TempCo="25 ppm/C", Tolerance_%=0.1%, Value2=0.1W, Value_Code=100k
R8 R10 R12 R15 R16 R17: library part CMP-0025736-4, "RES, 1.0 M, 5%, 0.1 W, AEC-Q200 Grade 0, 0603", Manufacturer=Vishay-Dale, Power_W=100mW, Supplier Part Number 1=541-1.0MGCT-ND, TempCo="200 ppm/C", Tolerance_%=5%, Value2=0.1W, Value_Code=1M00, ValueDisplayed=1.0M
R9: library part CMP-0024304-2, "RES, 4.99 k, 0.1%, 0.1 W, 0603", Manufacturer="Yageo America", Power_W=100mW, TempCo="25 ppm/C", Tolerance_%=0.1%, Value2=0.1W, Value_Code=4k99, ValueDisplayed=4.99k
R11: library part CMP-0025329-3, "RES, 499 k, 0.5%, 0.1 W, 0603", Manufacturer="Yageo America", Power_W=100mW, TempCo="50 ppm/C", Tolerance_%=0.5%, Value2=0.1W, Value_Code=499k
R13 R23: library part CMP-0019777-2, "RES, 20.0, 0.1%, 0.125 W, 0805", Manufacturer="Yageo America", Power_W=125mW, Supplier Part Number 1=9982892, TempCo="25 ppm/C", Tolerance_%=0.1%, Value2=0.125W, Value_Code=20R0, ValueDisplayed=20.0
R18 R19 R20 R21: library part CMP-0080488-1, "RES, 10.0 k, 1%, 0.1 W, 0603", Manufacturer="TT Electronics/IRC", Power_W=100mW, TempCo="100 ppm/C", Tolerance_%=1%, Value2=0.1W, Value_Code=10k0, ValueDisplayed=10.0k
R22: library part CMP-0081973-1, "RES, 0, 0%, 0.25 W, AEC-Q200 Grade 0, 0603", Manufacturer=Vishay-Dale, Power_W=250mW, Supplier Part Number 1=541-2779-1-ND, Tolerance_%=0%, Value2=0.25W, Value_Code=0
SH-J1 SH-J2 SH-J3 SH-J4 SH-J5 SH-J6: library part CMP-0003761-2, "Shunt, 2.54mm, Gold, Black", Manufacturer="Wurth Elektronik", Supplier Part Number 1=732-2678-ND
TP1: library part CMP-0003719-1, "Testpoint", Manufacturer="Texas Instruments"
TP2 TP3 TP4: library part CMP-0055139-2, "Test Point, Miniature, White, TH", Color=White, Manufacturer="Keystone Electronics", PartNumber=5002, Supplier Part Number 1=36-5002-ND
U1: library part CMP-0123072-1, "Nanopower-IQ 200nA 200mA low-dropout (LDO) voltage regulator with fast transient response", Digikey Part Number=296-TPS7A0333DBVRCT-ND, Dropout Voltage=310mV, Manufacturer="Texas Instruments", Max Supply Voltage=6V, Min Supply Voltage=3.8V, Mouser Part Number=595-TPS7A0333DBVR, Nominal Supply Current=0.2uA, Operating Temperature Range="-40°C to +125°C", Output Voltage=3.3V
U2: library part CMP-0097920-1, "Ultra Low-Power, High-Precision Voltage Reference", Digikey Part Number=296-REF35125QDBVRTR-ND, Manufacturer="Texas Instruments", Max Supply Voltage=6V, Min Supply Voltage=1.75V, Mouser Part Number=595-REF35125QDBVR, Nominal Supply Current=0.65uA, Operating Temperature Range="-40°C to +125°C", Output Voltage=1.25V
U3: library part CMP-0123071-1, "Nanopower-IQ 200nA 200mA low-dropout (LDO) voltage regulator with fast transient response 5-SOT-23 -40 to 125", Digikey Part Number=296-TPS7A0318DBVRCT-ND, Dropout Voltage=450mV, Manufacturer="Texas Instruments", Max Supply Voltage=6V, Min Supply Voltage=2.3V, Mouser Part Number=595-TPS7A0318DBVR, Nominal Supply Current=0.2uA, Operating Temperature Range="-40°C to +125°C", Output Voltage=1.8V
U4: library part CMP-0096723-1, Manufacturer="Texas Instruments", Operating Temperature Range=to
U5: library part CMP-0094597-1, "General Purpose Amplifier 1 Circuit Rail-to-Rail SC-70-5", Digikey Part Number=296-OPA391DCKTCT-ND, Input Bias Current=0.00000001uA, Input Offset Voltage=0.06mV, Manufacturer="Texas Instruments", Max Dual Supply Voltage=2.75V, Max Supply Voltage=5.5V, Min Dual Supply Voltage=850mV, Min Supply Voltage=1.7V, Mouser Part Number=595-OPA391DCKT, Nominal Supply Current=24uA, Operating Temperature Range="-40°C to +125°C", Output Current Per Channel=60mA, Voltage Gain=121dB
U6: library part CMP-0081715-3, "33 V Bidirectional Flat-Clamp Surge Protection Device, DRB0008A (VSON-8)", Alternate Manufacturer="Texas Instruments", Alternate PartNumber=TVS3301DRBT, Operating Temperature Range="-40 to 125 C", Rating=Catalog
U7: library part CMP-0123563-1, "1.65-V to 5.5-V 8-bit parallel-load shift register with voltage translation", Digikey Part Number=296-SN74LV8T165BQBRCT-ND, Frequency_Fixed=37.7MHz, Manufacturer="Texas Instruments", Max Supply Voltage=5.5V, Min Supply Voltage=1.65V, Mouser Part Number=595-SN74LV8T165BQBR, Nominal Supply Current=2uA, Operating Temperature Range="-40°C to +125°C"
U8: library part CMP-0860319-1, "1-ch, 2:1 general-purpose analog multiplexer with 1.8-V logic control, DCK0006A (SOT-SC70-6)", Alternate Manufacturer="Texas Instruments", Operating Temperature Range="-40 to 125 C", Rating=Catalog
ZZ1: library part CMP-0003616-3
ZZ2: library part CMP-0077236-1
ZZ3: library part CMP-0077237-1
ZZ4: library part CMP-0077238-1

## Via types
v1: diameter 24, hole 8, Top Layer to Bottom Layer, tented both sides, 65 vias
v2: diameter 19.68, hole 7.87, Top Layer to Bottom Layer, 16 vias
v3: diameter 20, hole 8, Top Layer to Bottom Layer, tented both sides, 9 vias
v4: diameter 19.68, hole 7.87, Top Layer to Bottom Layer, tented both sides, 4 vias
v5: diameter 28, hole 12, Top Layer to Bottom Layer, tented both sides, 1 vias

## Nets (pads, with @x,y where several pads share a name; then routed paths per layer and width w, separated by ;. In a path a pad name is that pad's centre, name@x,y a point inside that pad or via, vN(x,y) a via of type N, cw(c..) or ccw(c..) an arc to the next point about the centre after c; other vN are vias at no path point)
AIN0: U4.15
ALARM: J1.11 R21.1 U4.24 | length 2004.1
  Top Layer w6: J1.11@160.52,453.39 114.65,407.52 114.65,215.35 150,180 583.85,180 693.85,70 961,70 971,60 1030,60 1079.96,109.96 v1@1079.96,140.07 ; U4.24@965.82,453.77 967.74,455.69 967.88,455.69 967.88,464.17 994.38,490.67 v1(1016.73,490.67)
  Bottom Layer w6: J1.11@160.52,453.39 207.13,500 R21.1@328.5,500 ; R21.1@320.9,506.11 R21.1@323.99,503.02 ; R21.1@323.33,493.33 R21.1@341.84,493.33 ; v1(1016.73,490.67) 1016.73,459 1005.29,447.57 1005.29,254.41 1081.83,177.87 v1(1081.83,141.85)
CD: J1.13 R16.1 U4.3 | length 1699.1
  Top Layer w6: J1.13@160.52,353.39 213.09,300.83 557.16,300.83 727.99,130 979.51,130 982.46,132.96 996.56,132.96 v1(1000,136.4) ; U4.3@902.83,477.39 902.83,502.93 906.02,506.12 906.02,525.07 902.83,528.26 v3(902.83,550.09)
  Bottom Layer w6: J1.13@160.52,353.39 207.13,400 308.3,400 311.82,396.49 311.82,395.7 327.52,380 R16.1@328.5,380 ; v3(902.83,550.09) 902.83,515.53 956.61,461.74 956.61,337.91 934.87,316.17 934.87,165.48 963.95,136.4 v1(1000,136.4)
CS: J1.12 R15.1 U4.10 | length 678.8
  Top Layer w6: J1.12@260.52,453.39 335.94,377.98 745.37,377.98 762.1,394.71 U4.10@820.15,394.71
  Bottom Layer w6: J1.12@260.52,453.39 268.87,461.74 306.77,461.74 311.82,456.69 311.82,455.7 327.52,440 R15.1@328.5,440
"DAC HART RX": J1.16 U4.2 | length 1411.4
  Top Layer w6: J1.16@260.52,253.39 576.06,253.39 719.6,109.85 1019.83,109.85 1046.38,136.4 v1(1046.38,166.5) ; U4.2@922.51,477.39 922.51,527.99 944.61,550.09 v3(944.61,553.39)
  Bottom Layer w6: v3(944.61,553.39) 961.66,553.39 980.61,534.43 980.61,308.29 979.59,307.26 979.59,236.94 1046.38,170.15 v1(1046.38,166.5)
"DAC HART TX": J1.14 U4.1 | length 1223.3
  Top Layer w6: J1.14@260.52,353.39 533.11,353.39 737.04,149.45 969.45,149.45 v1(1000,180) ; U4.1@942.2,477.39 943.48,478.68 943.48,494.38 955.22,506.11 v3(956.61,506.11)
  Bottom Layer w6: v3(956.61,506.11) 956.61,503.24 968.61,491.24 968.61,313.26 960,304.65 960,220 v1(1000,180)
